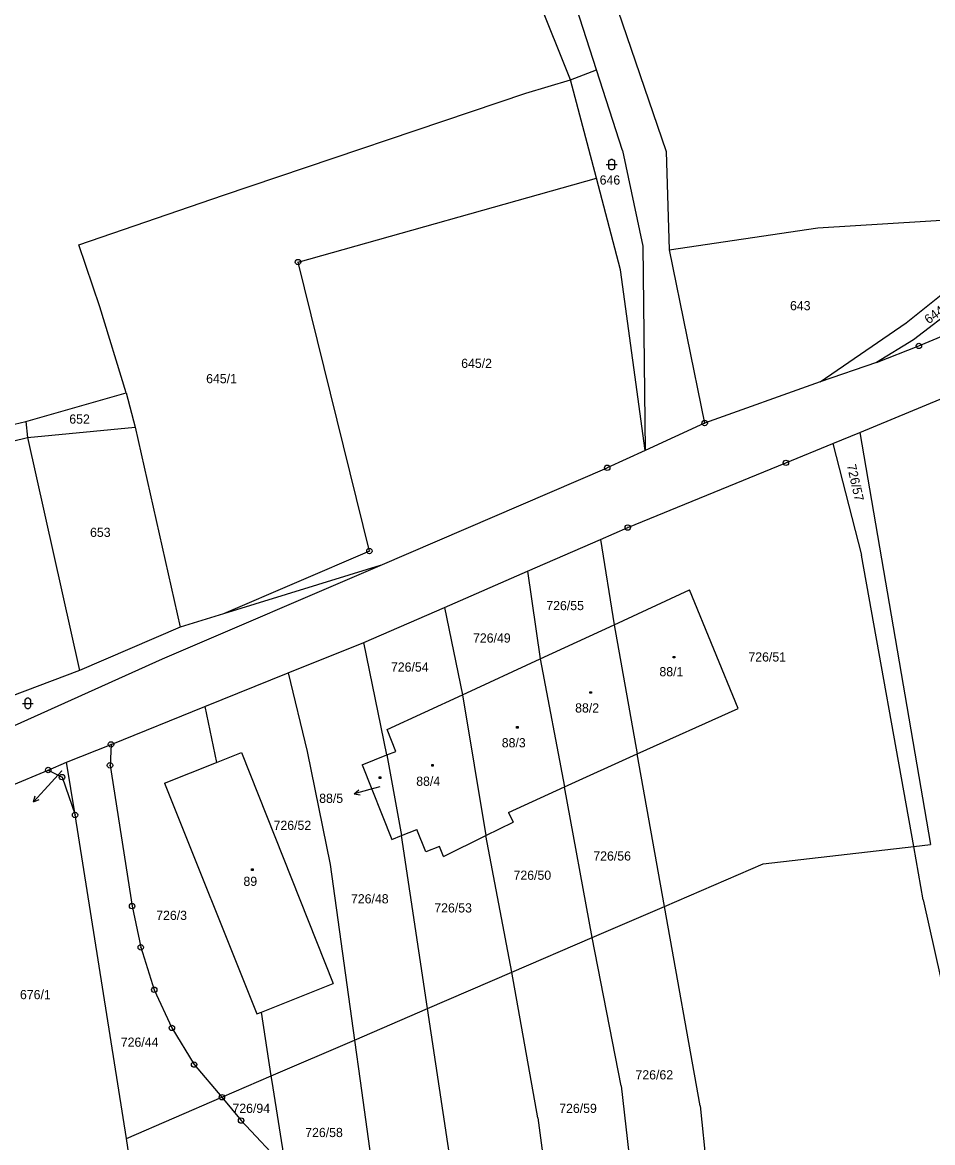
# Model space of a CAD drawing. Extents: x -794142 to -791199, y -1109267 to -1105626.
# Drawn here: x -793312.7 to -793144.4, y -1107639.7 to -1107432.6 of the extents above; entities that cross this region are included whole.
import ezdxf

# ---------------------------------------------------------------- set-up
doc = ezdxf.new("R2010")
doc.units = 0
for name, color, linetype in [('Komunikace', 7, 'Continuous'), ('Vrstva 1', 7, 'Continuous'), ('Vrstva 14', 7, 'Continuous'), ('Vrstva 15', 7, 'Continuous'), ('Vrstva 16', 7, 'Continuous'), ('Vrstva 23', 7, 'Continuous'), ('Vrstva 25', 7, 'Continuous'), ('Vrstva 28', 7, 'Continuous')]:
    doc.layers.add(name, color=color, linetype=linetype)

msp = doc.modelspace()

# ---------------------------------------------------------------- linework, layer by layer
at = {"layer": 'Komunikace'}
for p, q in [((-793305.38, -1107570.94), (-793308.62, -1107574.45)), ((-793246.62, -1107573.89), (-793248.43, -1107574.39))]:
    msp.add_line(p, q, dxfattribs=at)
at = {"layer": 'Vrstva 1'}
for p, q in [((-793207.57, -1107415.64), (-793193.67, -1107456.42)), ((-793206.52, -1107441.36), (-793213.79, -1107418.78)), ((-793211.37, -1107443.17), (-793220.18, -1107421.06)), ((-793211.37, -1107443.17), (-793206.52, -1107441.36)), ((-793201.72, -1107456.26), (-793206.52, -1107441.36)), ((-793219.58, -1107445.67), (-793211.37, -1107443.17)), ((-793206.56, -1107461.35), (-793211.37, -1107443.17)), ((-793275.49, -1107464.53), (-793219.58, -1107445.67)), ((-793201.72, -1107456.26), (-793197.98, -1107473.95)), ((-793193.67, -1107456.42), (-793193.12, -1107474.62)), ((-793261.73, -1107476.88), (-793206.56, -1107461.35)), ((-793202.07, -1107478.29), (-793206.56, -1107461.35)), ((-793302.27, -1107473.68), (-793275.49, -1107464.53)), ((-793165.61, -1107470.53), (-793124.17, -1107467.99)), ((-793149.26, -1107488.09), (-793124.17, -1107467.99)), ((-793193.12, -1107474.62), (-793165.61, -1107470.53)), ((-793122.23, -1107471.56), (-793147.93, -1107491.25)), ((-793298.37, -1107485.16), (-793302.27, -1107473.68)), ((-793197.98, -1107473.95), (-793197.56, -1107511.75)), ((-793193.12, -1107474.62), (-793186.53, -1107506.65)), ((-793248.53, -1107530.31), (-793261.73, -1107476.88)), ((-793146.92, -1107492.39), (-793110.61, -1107477.03)), ((-793197.56, -1107511.75), (-793202.07, -1107478.29)), ((-793293.52, -1107501.05), (-793298.37, -1107485.16)), ((-793165.17, -1107499.01), (-793149.26, -1107488.09)), ((-793147.93, -1107491.25), (-793154.77, -1107495.43)), ((-793154.77, -1107495.43), (-793146.92, -1107492.39)), ((-793154.77, -1107495.43), (-793165.17, -1107499.01)), ((-793165.17, -1107499.01), (-793186.53, -1107506.65)), ((-793157.84, -1107508.37), (-793135.99, -1107499.3)), ((-793312.08, -1107506.35), (-793293.52, -1107501.05)), ((-793293.52, -1107501.05), (-793291.87, -1107507.39)), ((-793338.94, -1107512.75), (-793312.08, -1107506.35)), ((-793312.08, -1107506.35), (-793311.77, -1107509.33)), ((-793311.77, -1107509.33), (-793291.87, -1107507.39)), ((-793291.87, -1107507.39), (-793283.51, -1107544.4)), ((-793186.53, -1107506.65), (-793197.56, -1107511.75)), ((-793162.84, -1107510.43), (-793157.84, -1107508.37)), ((-793157.84, -1107508.37), (-793144.77, -1107584.56)), ((-793338.31, -1107515.86), (-793311.77, -1107509.33)), ((-793311.77, -1107509.33), (-793302.15, -1107552.37)), ((-793171.51, -1107514), (-793162.84, -1107510.43)), ((-793162.84, -1107510.43), (-793157.55, -1107531.07)), ((-793197.56, -1107511.75), (-793204.54, -1107514.92)), ((-793200.76, -1107525.96), (-793171.51, -1107514)), ((-793246.53, -1107532.96), (-793204.54, -1107514.92)), ((-793205.82, -1107528.16), (-793200.76, -1107525.96)), ((-793219.27, -1107534.02), (-793205.82, -1107528.16)), ((-793205.82, -1107528.16), (-793203.28, -1107543.95)), ((-793248.53, -1107530.31), (-793275.49, -1107541.92)), ((-793147.88, -1107584.92), (-793157.55, -1107531.07)), ((-793286.77, -1107550.24), (-793246.53, -1107532.96)), ((-793246.53, -1107532.96), (-793275.49, -1107541.92)), ((-793234.64, -1107540.72), (-793219.27, -1107534.02)), ((-793219.27, -1107534.02), (-793216.93, -1107550.25)), ((-793203.28, -1107543.95), (-793189.31, -1107537.51)), ((-793180.33, -1107559.42), (-793189.31, -1107537.51)), ((-793249.55, -1107547.21), (-793234.64, -1107540.72)), ((-793234.64, -1107540.72), (-793231.33, -1107556.89)), ((-793275.49, -1107541.92), (-793283.51, -1107544.4)), ((-793283.51, -1107544.4), (-793302.15, -1107552.37)), ((-793216.93, -1107550.25), (-793203.28, -1107543.95)), ((-793203.28, -1107543.95), (-793199.01, -1107567.81)), ((-793263.54, -1107552.86), (-793249.55, -1107547.21)), ((-793245.31, -1107568.02), (-793249.55, -1107547.21)), ((-793318.83, -1107564.67), (-793286.77, -1107550.24)), ((-793231.33, -1107556.89), (-793216.93, -1107550.25)), ((-793216.93, -1107550.25), (-793212.43, -1107573.91)), ((-793302.15, -1107552.37), (-793327.5, -1107562.01)), ((-793278.98, -1107559.08), (-793263.54, -1107552.86)), ((-793263.54, -1107552.86), (-793260.03, -1107567.35)), ((-793245.25, -1107563.31), (-793231.33, -1107556.89)), ((-793231.33, -1107556.89), (-793227, -1107582.92)), ((-793296.31, -1107566.06), (-793278.98, -1107559.08)), ((-793278.98, -1107559.08), (-793276.82, -1107569.39)), ((-793199.01, -1107567.81), (-793180.33, -1107559.42)), ((-793243.64, -1107567.36), (-793245.25, -1107563.31)), ((-793304.51, -1107569.36), (-793296.31, -1107566.06)), ((-793296.31, -1107566.06), (-793296.49, -1107569.94)), ((-793276.82, -1107569.39), (-793272.19, -1107567.55)), ((-793272.19, -1107567.55), (-793255.21, -1107610.29)), ((-793260.03, -1107567.35), (-793255.78, -1107588.3)), ((-793249.87, -1107569.82), (-793245.31, -1107568.02)), ((-793245.31, -1107568.02), (-793243.64, -1107567.36)), ((-793245.31, -1107568.02), (-793242.59, -1107582.91)), ((-793212.43, -1107573.91), (-793199.01, -1107567.81)), ((-793193.96, -1107596.02), (-793199.01, -1107567.81)), ((-793307.92, -1107570.8), (-793304.51, -1107569.36)), ((-793302.96, -1107579.11), (-793304.51, -1107569.36)), ((-793296.49, -1107569.94), (-793292.42, -1107595.96)), ((-793286.44, -1107573.21), (-793276.82, -1107569.39)), ((-793249.87, -1107569.82), (-793244.4, -1107583.63)), ((-793315.01, -1107573.81), (-793307.92, -1107570.8)), ((-793307.92, -1107570.8), (-793305.37, -1107572.11)), ((-793305.37, -1107572.11), (-793302.96, -1107579.11)), ((-793286.44, -1107573.21), (-793269.35, -1107615.91)), ((-793222.81, -1107578.63), (-793212.43, -1107573.91)), ((-793207.32, -1107601.78), (-793212.43, -1107573.91)), ((-793222.81, -1107578.63), (-793221.93, -1107580.43)), ((-793293.47, -1107638.91), (-793302.96, -1107579.11)), ((-793227, -1107582.92), (-793221.93, -1107580.43)), ((-793244.4, -1107583.63), (-793242.59, -1107582.91)), ((-793242.59, -1107582.91), (-793239.73, -1107581.78)), ((-793237.77, -1107614.9), (-793242.59, -1107582.91)), ((-793238.09, -1107585.92), (-793239.73, -1107581.78)), ((-793234.85, -1107586.78), (-793227, -1107582.92)), ((-793222.21, -1107608.19), (-793227, -1107582.92)), ((-793235.58, -1107584.92), (-793238.09, -1107585.92)), ((-793234.85, -1107586.78), (-793235.58, -1107584.92)), ((-793175.72, -1107588.15), (-793147.88, -1107584.92)), ((-793147.88, -1107584.92), (-793144.77, -1107584.56)), ((-793146.1, -1107594.81), (-793147.88, -1107584.92)), ((-793255.78, -1107588.3), (-793251.27, -1107620.72)), ((-793193.96, -1107596.02), (-793175.72, -1107588.15)), ((-793146.1, -1107594.81), (-793138.02, -1107631.23)), ((-793292.42, -1107595.96), (-793290.81, -1107603.58)), ((-793207.32, -1107601.78), (-793193.96, -1107596.02)), ((-793187.36, -1107632.9), (-793193.96, -1107596.02)), ((-793290.81, -1107603.58), (-793288.31, -1107611.44)), ((-793222.21, -1107608.19), (-793207.32, -1107601.78)), ((-793201.98, -1107629.19), (-793207.32, -1107601.78)), ((-793237.77, -1107614.9), (-793222.21, -1107608.19)), ((-793217.4, -1107635.09), (-793222.21, -1107608.19)), ((-793288.31, -1107611.44), (-793285.05, -1107618.49)), ((-793268.5, -1107615.57), (-793255.21, -1107610.29)), ((-793269.35, -1107615.91), (-793268.5, -1107615.57)), ((-793266.67, -1107627.36), (-793268.5, -1107615.57)), ((-793251.27, -1107620.72), (-793237.77, -1107614.9)), ((-793230.76, -1107661.51), (-793237.77, -1107614.9)), ((-793285.05, -1107618.49), (-793280.94, -1107625.27)), ((-793266.67, -1107627.36), (-793251.27, -1107620.72)), ((-793251.27, -1107620.72), (-793250.22, -1107628.24)), ((-793280.94, -1107625.27), (-793275.81, -1107631.3)), ((-793275.81, -1107631.3), (-793266.67, -1107627.36)), ((-793266.51, -1107628.37), (-793266.67, -1107627.36)), ((-793264, -1107644.35), (-793266.51, -1107628.37)), ((-793250.22, -1107628.24), (-793245.22, -1107664.26)), ((-793201.98, -1107629.19), (-793198.96, -1107655.94)), ((-793293.47, -1107638.91), (-793275.81, -1107631.3)), ((-793275.81, -1107631.3), (-793272.25, -1107635.61)), ((-793187.36, -1107632.9), (-793185.66, -1107649.42)), ((-793272.25, -1107635.61), (-793264, -1107644.35)), ((-793217.4, -1107635.09), (-793213.55, -1107663.1)), ((-793292.46, -1107645.29), (-793293.47, -1107638.91))]:
    msp.add_line(p, q, dxfattribs=at)
at = {"layer": 'Vrstva 16'}
for p, q in [((-793308.62, -1107574.45), (-793310.654, -1107576.654)), ((-793248.43, -1107574.39), (-793251.323, -1107575.184)), ((-793251.323, -1107575.184), (-793250.491, -1107574.437)), ((-793310.654, -1107576.654), (-793310.343, -1107575.58)), ((-793310.654, -1107576.654), (-793309.609, -1107576.258)), ((-793251.323, -1107575.184), (-793250.226, -1107575.401))]:
    msp.add_line(p, q, dxfattribs=at)
at = {"layer": 'Vrstva 23'}
for p, q in [((-793204.23, -1107458.25), (-793204.13, -1107458.05)), ((-793204.23, -1107459.45), (-793204.23, -1107458.25)), ((-793204.13, -1107458.05), (-793204.03, -1107457.95)), ((-793204.03, -1107457.95), (-793203.83, -1107457.85)), ((-793203.83, -1107457.85), (-793203.63, -1107457.85)), ((-793203.63, -1107457.85), (-793203.43, -1107457.95)), ((-793203.43, -1107457.95), (-793203.33, -1107458.05)), ((-793203.33, -1107458.05), (-793203.23, -1107458.25)), ((-793203.23, -1107458.25), (-793203.23, -1107459.45)), ((-793204.73, -1107458.85), (-793202.73, -1107458.85)), ((-793204.13, -1107459.65), (-793204.23, -1107459.45)), ((-793204.03, -1107459.75), (-793204.13, -1107459.65)), ((-793203.83, -1107459.85), (-793204.03, -1107459.75)), ((-793203.63, -1107459.85), (-793203.83, -1107459.85)), ((-793203.43, -1107459.75), (-793203.63, -1107459.85)), ((-793203.33, -1107459.65), (-793203.43, -1107459.75)), ((-793203.23, -1107459.45), (-793203.33, -1107459.65)), ((-793312.19, -1107557.88), (-793312.09, -1107557.68)), ((-793312.19, -1107559.08), (-793312.19, -1107557.88)), ((-793312.09, -1107557.68), (-793311.99, -1107557.58)), ((-793311.99, -1107557.58), (-793311.79, -1107557.48)), ((-793311.79, -1107557.48), (-793311.59, -1107557.48)), ((-793311.59, -1107557.48), (-793311.39, -1107557.58)), ((-793311.39, -1107557.58), (-793311.29, -1107557.68)), ((-793311.29, -1107557.68), (-793311.19, -1107557.88)), ((-793311.19, -1107557.88), (-793311.19, -1107559.08)), ((-793312.69, -1107558.48), (-793310.69, -1107558.48)), ((-793312.09, -1107559.28), (-793312.19, -1107559.08)), ((-793311.99, -1107559.38), (-793312.09, -1107559.28)), ((-793311.79, -1107559.48), (-793311.99, -1107559.38)), ((-793311.59, -1107559.48), (-793311.79, -1107559.48)), ((-793311.39, -1107559.38), (-793311.59, -1107559.48)), ((-793311.29, -1107559.28), (-793311.39, -1107559.38)), ((-793311.19, -1107559.08), (-793311.29, -1107559.28))]:
    msp.add_line(p, q, dxfattribs=at)
at = {"layer": 'Vrstva 25'}
for p, q in [((-793192.34, -1107549.78), (-793192.04, -1107549.78)), ((-793192.34, -1107550.08), (-793192.34, -1107549.78)), ((-793192.04, -1107549.78), (-793192.04, -1107550.08)), ((-793192.04, -1107550.08), (-793192.34, -1107550.08)), ((-793207.77, -1107556.32), (-793207.47, -1107556.32)), ((-793207.77, -1107556.62), (-793207.77, -1107556.32)), ((-793207.47, -1107556.62), (-793207.77, -1107556.62)), ((-793207.47, -1107556.32), (-793207.47, -1107556.62)), ((-793221.3, -1107562.74), (-793221, -1107562.74)), ((-793221.3, -1107563.04), (-793221.3, -1107562.74)), ((-793221, -1107563.04), (-793221.3, -1107563.04)), ((-793221, -1107562.74), (-793221, -1107563.04)), ((-793237.01, -1107569.77), (-793236.71, -1107569.77)), ((-793237.01, -1107570.07), (-793237.01, -1107569.77)), ((-793236.71, -1107570.07), (-793237.01, -1107570.07)), ((-793236.71, -1107569.77), (-793236.71, -1107570.07)), ((-793246.73, -1107572.06), (-793246.43, -1107572.06)), ((-793246.73, -1107572.36), (-793246.73, -1107572.06)), ((-793246.43, -1107572.36), (-793246.73, -1107572.36)), ((-793246.43, -1107572.06), (-793246.43, -1107572.36)), ((-793270.31, -1107589.07), (-793270.01, -1107589.07)), ((-793270.31, -1107589.37), (-793270.31, -1107589.07)), ((-793270.01, -1107589.07), (-793270.01, -1107589.37)), ((-793270.01, -1107589.37), (-793270.31, -1107589.37))]:
    msp.add_line(p, q, dxfattribs=at)
at = {"layer": 'Vrstva 28'}
for centre, radius in [((-793261.73, -1107476.88), 0.5), ((-793261.73, -1107476.88), 0.01), ((-793146.92, -1107492.39), 0.5), ((-793146.92, -1107492.39), 0.01), ((-793186.53, -1107506.65), 0.5), ((-793186.53, -1107506.65), 0.01), ((-793204.54, -1107514.92), 0.5), ((-793171.51, -1107514), 0.5), ((-793171.51, -1107514), 0.01), ((-793204.54, -1107514.92), 0.01), ((-793200.76, -1107525.96), 0.5), ((-793200.76, -1107525.96), 0.01), ((-793248.53, -1107530.31), 0.5), ((-793248.53, -1107530.31), 0.01), ((-793296.31, -1107566.06), 0.5), ((-793296.31, -1107566.06), 0.01), ((-793307.92, -1107570.8), 0.5), ((-793296.49, -1107569.94), 0.5), ((-793296.49, -1107569.94), 0.01), ((-793307.92, -1107570.8), 0.01), ((-793305.37, -1107572.11), 0.5), ((-793305.37, -1107572.11), 0.01), ((-793302.96, -1107579.11), 0.5), ((-793302.96, -1107579.11), 0.01), ((-793292.42, -1107595.96), 0.5), ((-793292.42, -1107595.96), 0.01), ((-793290.81, -1107603.58), 0.5), ((-793290.81, -1107603.58), 0.01), ((-793288.31, -1107611.44), 0.5), ((-793288.31, -1107611.44), 0.01), ((-793285.05, -1107618.49), 0.5), ((-793285.05, -1107618.49), 0.01), ((-793280.94, -1107625.27), 0.5), ((-793280.94, -1107625.27), 0.01), ((-793275.81, -1107631.3), 0.5), ((-793275.81, -1107631.3), 0.01), ((-793272.25, -1107635.61), 0.5), ((-793272.25, -1107635.61), 0.01)]:
    msp.add_circle(centre, radius, dxfattribs=at)

# ---------------------------------------------------------------- texts
at = {"layer": 'Vrstva 14'}
for s, height, p in [('646', 1.7, (-793205.943, -1107462.55)), ('643', 1.7, (-793170.743, -1107485.79)), ('645/2', 1.7, (-793231.552, -1107496.46)), ('645/1', 1.7, (-793278.715, -1107499.28)), ('652', 1.7, (-793304.023, -1107506.76)), ('653', 1.7, (-793300.183, -1107527.7)), ('726/55', 1.7, (-793215.809, -1107541.24)), ('726/49', 1.7, (-793229.362, -1107547.24)), ('726/51', 1.7, (-793178.436, -1107550.74)), ('726/54', 1.7, (-793244.538, -1107552.61)), ('676/12', 0.1, (-793305.618, -1107570.94)), ('726/52', 1.7, (-793266.242, -1107581.87)), ('726/56', 1.7, (-793207.113, -1107587.54)), ('726/50', 1.7, (-793221.872, -1107591.1)), ('726/48', 1.7, (-793251.932, -1107595.46)), ('726/53', 1.7, (-793236.523, -1107597.14)), ('726/3', 1.7, (-793287.946, -1107598.52)), ('676/1', 1.7, (-793313.14, -1107613.17)), ('726/44', 1.7, (-793294.498, -1107621.97)), ('726/62', 1.7, (-793199.316, -1107628.01)), ('726/94', 1.7, (-793273.852, -1107634.2)), ('726/59', 1.7, (-793213.423, -1107634.21)), ('726/58', 1.7, (-793260.392, -1107638.67))]:
    msp.add_text(s, height=height, dxfattribs=at).set_placement(p)
for s, rotation, p in [('644/2', 36.50616, (-793145.102, -1107488.409)), ('726/57', 282.86658, (-793160.25, -1107514.449))]:
    msp.add_text(s, height=1.7, rotation=rotation, dxfattribs=at).set_placement(p)
at = {"layer": 'Vrstva 15'}
for s, height, p in [('88/1', 1.7, (-793194.893, -1107553.47)), ('88/2', 1.7, (-793210.479, -1107560.17)), ('88/3', 1.7, (-793224.05, -1107566.61)), ('88/4', 1.7, (-793239.866, -1107573.72)), ('88/5', 0.1, (-793246.781, -1107573.89)), ('89', 1.7, (-793271.817, -1107592.23))]:
    msp.add_text(s, height=height, dxfattribs=at).set_placement(p)
at = {"layer": 'Vrstva 16'}
msp.add_text('88/5', height=1.7, dxfattribs=at).set_placement((-793257.812, -1107576.88))

doc.saveas('drawing.dxf')
